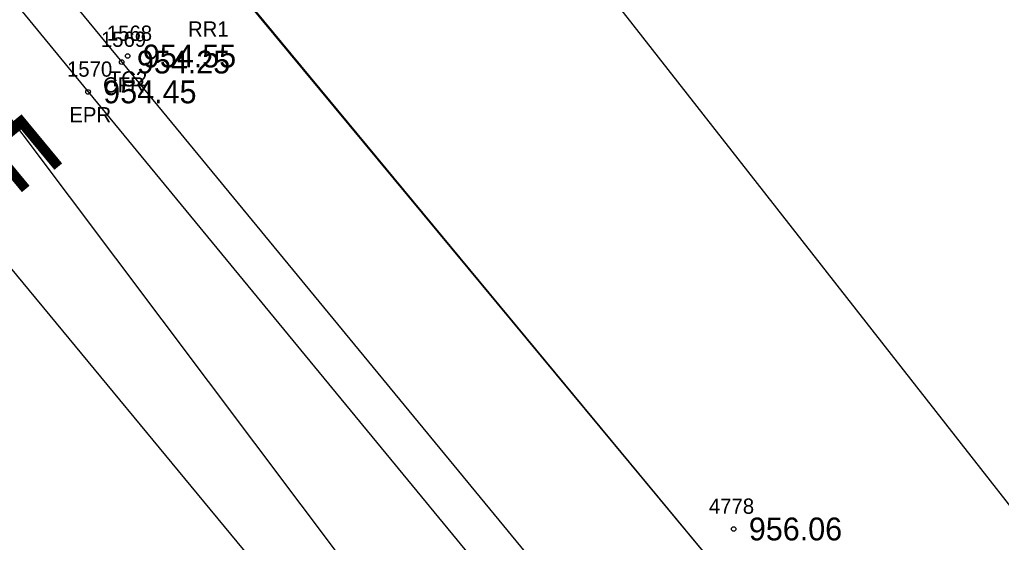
# Model space of a CAD drawing. Extents: x 1575382 to 1578175, y 1099175 to 1101955.
# Drawn here: x 1576509.8 to 1576574.4, y 1099467.4 to 1099501.7 of the extents above; entities that cross this region are included whole.
import ezdxf

# ---------------------------------------------------------------- set-up
doc = ezdxf.new("R2010")
doc.units = 0
for name, color, linetype in [('RD_EX_Conc', 7, 'Continuous'), ('RD_EX_Conc_txCode', 7, 'Continuous'), ('RD_EX_Misc', 7, 'Continuous'), ('RD_EX_RailRoad', 7, 'Continuous'), ('RD_EX_RailRoad_txCode', 7, 'Continuous'), ('RD_EX_Road', 7, 'Continuous'), ('RD_EX_Road_txCode', 7, 'Continuous'), ('RD_EX_TX_Conc_ELEV', 7, 'Continuous'), ('RD_EX_TX_RailRoad_ELEV', 7, 'Continuous'), ('RD_EX_TX_Road_ELEV', 7, 'Continuous'), ('RD_EX_UT', 7, 'Continuous'), ('RD_HC_Cl', 7, 'Continuous'), ('RD_HC_Data', 7, 'Continuous'), ('RD_SMD_Locator', 7, 'Continuous')]:
    doc.layers.add(name, color=color, linetype=linetype)

msp = doc.modelspace()

# ---------------------------------------------------------------- linework, layer by layer
at = {"layer": 'RD_EX_Conc'}
msp.add_lwpolyline([(1576448.277, 1099581.238), (1576485.223, 1099536.886), (1576516.554, 1099498.954), (1576548.71, 1099459.944), (1576580.645, 1099421.453)], dxfattribs=at)
at = {"layer": 'RD_EX_Misc'}
msp.add_lwpolyline([(1576459.307, 1099612.415), (1576482.964, 1099596.802), (1576529.602, 1099538.767), (1576530.242, 1099526.831), (1576601.162, 1099436.407)], dxfattribs=at)
at = {"layer": 'RD_EX_RailRoad'}
msp.add_lwpolyline([(1576586.778, 1099428.105), (1576554.904, 1099466.707), (1576523.695, 1099504.276), (1576490.272, 1099544.766), (1576459.306, 1099582.088), (1576445.84, 1099598.336), (1576409.987, 1099641.437), (1576367.438, 1099692.664), (1576334.672, 1099732.084), (1576298.682, 1099775.456), (1576256.762, 1099825.945)], dxfattribs=at)
at = {"layer": 'RD_EX_Road'}
msp.add_lwpolyline([(1576443.749, 1099596.959), (1576443.043, 1099588.286), (1576448.277, 1099581.238), (1576446.02, 1099579.487), (1576482.91, 1099535.224), (1576514.34, 1099496.993), (1576546.165, 1099458.389), (1576578.5, 1099419.576)], dxfattribs=at)
at = {"layer": 'RD_EX_UT'}
msp.add_lwpolyline([(1576589.463, 1099388.646), (1576430.603, 1099599.811), (1576417.784, 1099616.336)], dxfattribs=at)
at = {"layer": 'RD_HC_Cl'}
for p, q in [((1576594.9, 1099418.511), (1576256.801, 1099825.977)), ((1576414.585, 1099599.722), (1576569.263, 1099412.94))]:
    msp.add_line(p, q, dxfattribs=at)
at = {"layer": 'RD_SMD_Locator'}
for centre in [(1576516.948, 1099499.351), (1576516.554, 1099498.954), (1576514.34, 1099496.993), (1576556.816, 1099468.272)]:
    msp.add_circle(centre, 0.15, dxfattribs=at)

# ---------------------------------------------------------------- texts
at = {"layer": 'RD_EX_Conc_txCode'}
for s, p in [('1568', (1576515.578, 1099500.351)), ('1569', (1576515.184, 1099499.954)), ('TC2', (1576515.704, 1099497.351)), ('CFR', (1576515.326, 1099496.954))]:
    msp.add_text(s, height=1, dxfattribs=at).set_placement(p)
at = {"layer": 'RD_EX_RailRoad_txCode'}
for s, p in [('RR1', (1576520.915, 1099500.626)), ('4778', (1576555.186, 1099469.272))]:
    msp.add_text(s, height=1, dxfattribs=at).set_placement(p)
at = {"layer": 'RD_EX_Road_txCode'}
for s, p in [('1570', (1576512.954, 1099497.993)), ('EPR', (1576513.111, 1099494.993))]:
    msp.add_text(s, height=1, dxfattribs=at).set_placement(p)
at = {"layer": 'RD_EX_TX_Conc_ELEV'}
for s, p in [('954.55', (1576517.948, 1099498.601)), ('954.25', (1576517.554, 1099498.204))]:
    msp.add_text(s, height=1.5, dxfattribs=at).set_placement(p)
at = {"layer": 'RD_EX_TX_RailRoad_ELEV'}
msp.add_text('956.06', height=1.5, dxfattribs=at).set_placement((1576557.816, 1099467.522))
at = {"layer": 'RD_EX_TX_Road_ELEV'}
msp.add_text('954.45', height=1.5, dxfattribs=at).set_placement((1576515.34, 1099496.243))
at = {"layer": 'RD_HC_Data'}
msp.add_text('S 39%%d 37\' 44" E', height=6, rotation=309.62881, dxfattribs=at).set_placement((1576473.907, 1099529.656))

doc.saveas('drawing.dxf')
